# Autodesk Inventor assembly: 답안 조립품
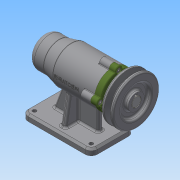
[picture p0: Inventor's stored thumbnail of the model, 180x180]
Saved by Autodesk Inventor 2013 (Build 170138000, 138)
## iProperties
Created: 2019-07
Part Number: 답안 조립품
Document SubType Name: Assembly
Designer: Administrator
Author: Administrator
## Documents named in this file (12)
- C:\Users\Administrator\Desktop\490704V1014\답안 조립품.iam
- C:\Users\Administrator\Desktop\490704V1014\본체.ipt
- C:\Users\Administrator\Desktop\490704V1014\V벨트풀리.ipt
- C:\Users\Administrator\Desktop\490704V1014\멈춤나사 M3.ipt
- C:\Users\Administrator\Desktop\490704V1014\베어링 6004.ipt
- C:\Users\Administrator\Desktop\490704V1014\베어링 51202.ipt
- C:\Users\Administrator\Desktop\490704V1014\볼트 M4.ipt
- C:\Users\Administrator\Desktop\490704V1014\어댑터슬리브.ipt
- C:\Users\Administrator\Desktop\490704V1014\오일 실.ipt
- C:\Users\Administrator\Desktop\490704V1014\축.ipt
- C:\Users\Administrator\Desktop\490704V1014\커버.ipt
- C:\Users\Administrator\Desktop\490704V1014\키 5 x 5 x 16.ipt
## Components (1 placed, 1 different names)
1. V벨트풀리:1
